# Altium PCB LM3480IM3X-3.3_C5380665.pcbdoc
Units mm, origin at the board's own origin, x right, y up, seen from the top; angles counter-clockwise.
Board outline 15.66 x 15.75 mm, 2 copper layers (Top Layer, Bottom Layer), stack 0 mm thick; 1 components, 0 nets, 3 pads, 0 vias.
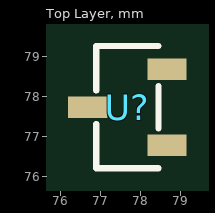
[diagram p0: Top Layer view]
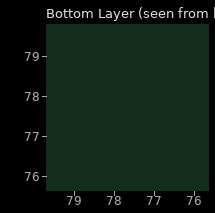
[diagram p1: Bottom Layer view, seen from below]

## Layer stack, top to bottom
Top Layer: signal copper (thickness not stored)
Bottom Layer: signal copper (thickness not stored)

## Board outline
85.506,69.85 69.85,69.85 69.85,85.602 85.506,85.602

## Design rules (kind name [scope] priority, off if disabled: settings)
PasteMaskExpansion "Paste Mask Expansion" [All] p1: expansion=0
SolderMaskExpansion "Solder Mask Expansion" [IsVia] p1: expansion=-25.4 istentingtop=TRUE
SolderMaskExpansion "Solder Mask Expansion" [All] p2: expansion=0.051 istentingtop=FALSE

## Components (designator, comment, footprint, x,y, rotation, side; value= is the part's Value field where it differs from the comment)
U? "LM3480IM3X-3.3" SOT-23-3_L2.9-W1.4-0.95-LS2.5-BR 77.678,77.726 r0 top

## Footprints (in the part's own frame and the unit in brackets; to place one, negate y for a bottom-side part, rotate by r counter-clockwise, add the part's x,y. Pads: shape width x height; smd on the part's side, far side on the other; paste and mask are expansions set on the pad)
SOT-23-3_L2.9-W1.4-0.95-LS2.5-BR [mm]
  rect 0.978x0.532 smd: 1(0.989,-0.95) 2(0.989,0.95) 3(-0.989,0)
  silkscreen extent -0.78,-1.53 0.78,1.53

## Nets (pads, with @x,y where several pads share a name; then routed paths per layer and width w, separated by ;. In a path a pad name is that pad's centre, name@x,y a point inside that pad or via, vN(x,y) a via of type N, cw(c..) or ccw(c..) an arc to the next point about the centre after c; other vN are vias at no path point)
pads on no net: U?.1 U?.2 U?.3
